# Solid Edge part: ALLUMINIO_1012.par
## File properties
Subject: ALLUMINIO_1012
Author: f_grande
Template: Normal.par
Last saved by: f_grande
Revision: 2
Application: Solid Edge
Material: Alluminio, 1060
Stile della faccia: Alluminio
Stile di riempimento: ANSI38(Alluminio)
Stile virtuale: Alluminio lucidato
Coef. of Thermal Exp: 0.0
Thermal Conductivity: 221.0
Specific Heat: 920.0
Modulus of Elasticity: 68947570000.0
Poisson's Ratio: 0.33
Yield Stress: 27579028.0
Ultimate Stress: 68947570.0
Elongation: 0.0
Tipo di contenuto documento: 0
Densità: 2712,000 kg/m^3
Precisione: 0,990
Document Number: KR0100
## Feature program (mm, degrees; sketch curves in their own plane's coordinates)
sketch for "unnamed Protrusion 1" #1 plane through (0, 0, 0) normal (0, -1, 0) x-axis (1, 0, 0)
  line (2.4, -2.4) -> (13.3, -2.4)
  line (13.3, -2.4) -> (13.3, -13.3)
  line (13.3, -13.3) -> (2.4, -13.3)
  line (2.4, -13.3) -> (2.4, -2.4)
sketch for "unnamed Protrusion 1" #2 plane through (0, 0, 0) normal (0, -1, 0) x-axis (1, 0, 0)
  line (18.3, 0) -> (18.3, -4.5)
  line (18.3, -4.5) -> (15.7, -4.5)
  line (15.7, -4.5) -> (15.7, -12.8)
  arc centre (18.7, -12.8) radius 3 from (18.7, -15.8) to (15.7, -12.8) cw
  line (18.7, -15.8) -> (22.5, -15.8)
  line (22.5, -15.8) -> (22.5, -19.1)
  line (22.5, -26.1) -> (22.5, -33.2)
  line (14.5, -33.2) -> (22.5, -33.2)
  line (14.5, -34.2) -> (14.5, -33.2)
  line (2.4, -34.2) -> (14.5, -34.2)
  line (2.4, -47.5) -> (2.4, -34.2)
  line (0, -47.5) -> (2.4, -47.5)
  line (0, -26.8) -> (0, -47.5)
  line (0, -26.8) -> (4.7588, -26.8)
  line (4.7588, -26.8) -> (4.7588, -29.0094)
  line (4.7588, -29.0094) -> (12.8, -29.0094)
  arc centre (12.8, -26.0094) radius 3 from (12.8, -29.0094) to (15.8, -26.0094) ccw
  line (15.8, -18.7) -> (15.8, -26.0094)
  arc centre (12.8, -18.7) radius 3 from (12.8, -15.7) to (15.8, -18.7) cw
  line (4.5, -15.7) -> (12.8, -15.7)
  line (4.5, -18.3) -> (4.5, -15.7)
  line (0, -18.3) -> (4.5, -18.3)
  line (0, -2.4) -> (0, -18.3)
  arc centre (2.4, -2.4) radius 2.4 from (2.4, 0) to (0, -2.4) ccw
  line (2.4, 0) -> (18.3, 0)
  dimension (linear) = 18.3
  dimension (linear) = 18.3
  dimension (linear) = 4.5
  dimension (linear) = 18.7
  dimension (linear) = 2.4
  dimension (linear) = 15.7
  dimension (linear) = 4.7588
  dimension (linear) = 4.7588
  dimension (linear) = 15.8
  dimension (linear) = 2.4
  dimension (linear) = 2.4
  dimension (linear) = 2.4
  dimension (linear) = 2.4
  dimension (linear) = 14.5
  dimension (linear) = 14.5
  dimension (linear) = 22.5
  dimension (linear) = 22.5
extrude "unnamed Protrusion 1" add finite 1012 along -normal
body pattern "unnamed BodyPattern 1"
pattern "unnamed Pattern 1"
body pattern "unnamed BodyPattern 2"
pattern "unnamed Pattern 2"
thread "unnamed Thread 1"
thread "unnamed Thread 2"
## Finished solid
Body 1: solid body, 100 faces, 292 edges, 192 vertices.
  Faces by surface: plane 82, cylinder 18
  Edges by curve: line 256, circle 36
Bounding box of the edges (mm): 45.000 x 1012.000 x 95.000, from (0, 0, -95) to (45, 1012, 0).
Cylindrical faces by radius (mm): R2.4 x4, R3 x12, R3.5 x2
Planar faces by outward normal: +x 20, +y 1, +z 20, -x 20, -y 1, -z 20
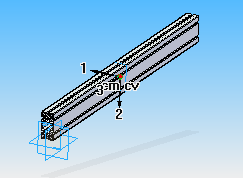
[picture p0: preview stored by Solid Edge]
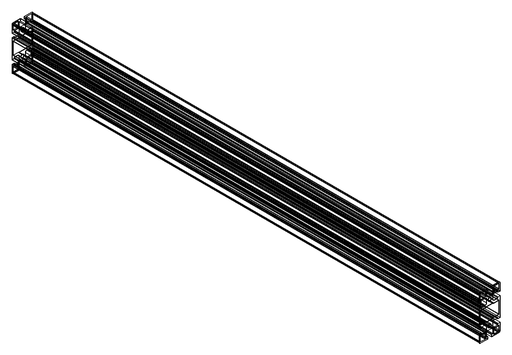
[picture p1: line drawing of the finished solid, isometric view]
